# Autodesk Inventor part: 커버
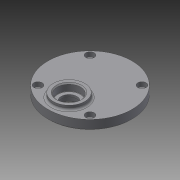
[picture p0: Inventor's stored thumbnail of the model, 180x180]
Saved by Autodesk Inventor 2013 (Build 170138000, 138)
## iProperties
Created: 2015-07
Part Number: 커버
Material: 일반
Document SubType Name: Modeling
Designer: user
Density: 1 g/cm^3
Author: user
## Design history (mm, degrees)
sketch "스케치1"
  geometry: C1 r 40 at (0, 0); 1 further point
  constraints: 1 centre point, 1 coincident
  dimensions: "d0" = 80 diameter of C1
extrude "돌출1" new body sketch "스케치1" distance "d1" = 9; taper "d2" = 0 deg
sketch "스케치2"
  geometry: L1 (0, -20)-(0, 0); C1 r 40 at (0, 0) reference; C2 r 15 at (0, -20)
  constraints: 2 end point, 1 centre point, 1 coincident, 1 vertical
  dimensions: "d3" = 20 distance of L1.start L1.end; "d4" = 30 diameter of C2
extrude "돌출2" join sketch "스케치2" distance "d5" = 4; taper "d6" = 0 deg
sketch "스케치3"
  geometry: L1 (0, 0)-(0, -20); L2 (0, 0)-(0, 11); C1 r 40 at (0, 0) reference; C2 r 14 at (0, -20); C3 r 14 at (0, 11)
  constraints: 4 end point, 2 centre point, 2 coincident, 1 collinear, 1 vertical
  dimensions: "d7" = 20 distance of L1.start L1.end; "d8" = 11 distance of L1.start L2.end; "d9" = 28 diameter of C2; "d10" = 28 diameter of C3
extrude "돌출3" join sketch "스케치3" distance "d11" = 3; taper "d12" = 0 deg
sketch "스케치4"
  geometry: C1 r 14 at (0, 0) reference; C2 r 11 at (0, 0); 1 further point
  constraints: 1 centre point, 1 coincident
  dimensions: "d13" = 22 diameter of C2
extrude "돌출4" cut sketch "스케치4" distance "d14" = 7; taper "d15" = 0 deg
sketch "스케치5"
  geometry: C1 r 9 at (0, 0); 2 further points
  constraints: 1 centre point, 1 coincident, 1 vertical alignment
  dimensions: "d16" = 18 diameter of C1
extrude "돌출5" cut sketch "스케치5" distance "d17" = 1; taper "d18" = 0 deg
fillet "모깎기1" dims "d19" = 0.3
fillet "모깎기2" dims "d20" = 2
sketch "스케치6"
  geometry: C1 r 14 at (0, 0) reference; C2 r 11 at (0, 0); 1 further point
  constraints: 1 centre point, 1 coincident
  dimensions: "d21" = 22 diameter of C2
extrude "돌출6" cut sketch "스케치6" distance "d22" = 7; taper "d23" = 0 deg
sketch "스케치7"
  geometry: C1 r 11 at (0, 0) reference; C2 r 7.5 at (0, 0); 1 further point
  constraints: 1 centre point, 1 coincident
  dimensions: "d24" = 15 diameter of C2
extrude "돌출7" cut sketch "스케치7" distance "d25" = 2; taper "d26" = 0 deg
sketch "스케치8"
  geometry: C1 r 7.5 at (0, 0) reference; C2 r 11 at (0, 0); 1 further point
  constraints: 1 centre point, 1 coincident
  dimensions: "d27" = 22 diameter of C2
extrude "돌출8" cut sketch "스케치8" distance "d28" = 7; taper "d29" = 0 deg
fillet "모깎기3" dims "d30" = 0.3
chamfer "모따기1" distance "d31" = 1; stored, may be unused: second distance "d32" = 2, angle "d33" = 45 deg
fillet "모깎기4" dims "d34" = 2
chamfer "모따기2" distance "d35" = 1; stored, may be unused: second distance "d36" = 2, angle "d37" = 45 deg
sketch "스케치9" dims "d38" = 70
  geometry: L1 (0, 0)-(28.284, 28.284); L2 (0, 0)-(40, 0); 2 further points
  constraints: 4 end point, 1 coincident, 1 equal length, 1 horizontal, 1 point on line, 5 other
  dimensions: "d39" = 45 deg angle of L2 L1
hole "구멍1" sketch "스케치9" at (24.749, 24.749) diameter "d40" = 4.5; stored, may be unused: countersink angle "d44" = 90 deg, drill point angle "d46" = 118 deg; dims "d41" = 6, "d42" = 8, "d43" = 4.4, "d45" = 8
node "솔리드1"
pattern_circular "원형 패턴1" dims angle "d48" = 360 deg
